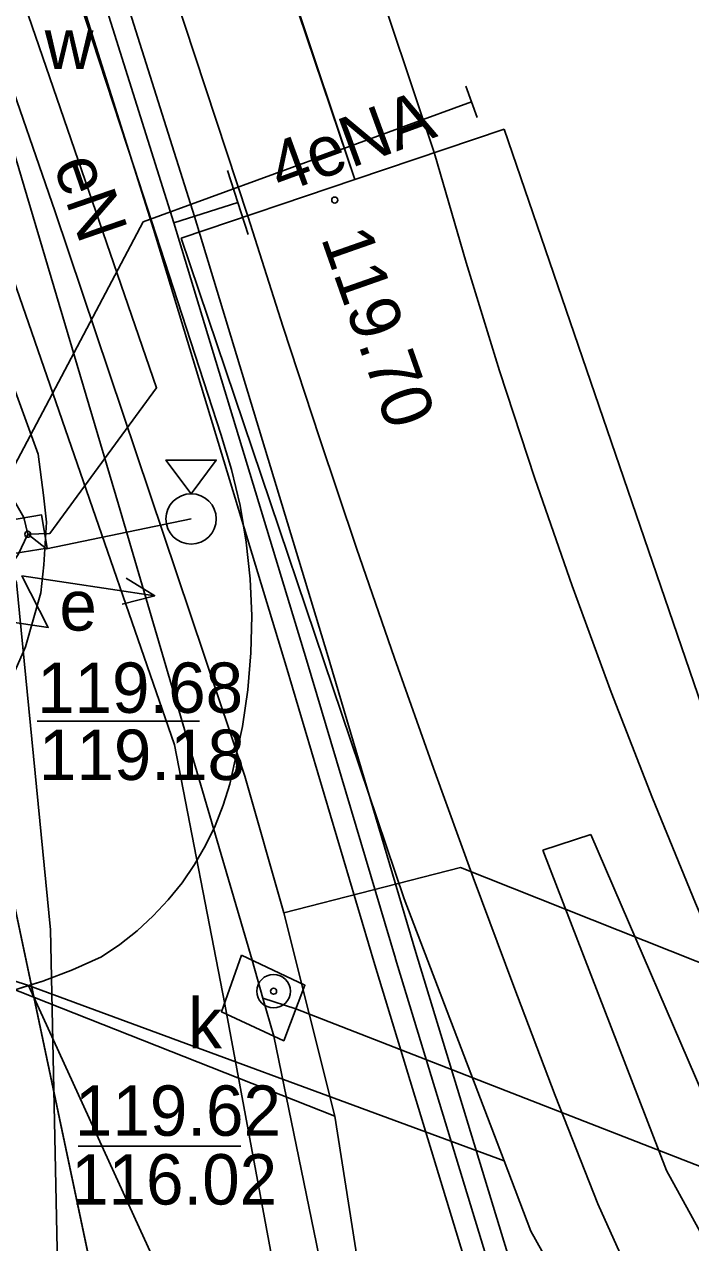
# Model space of a CAD drawing. Extents: x 6432121 to 6432331, y 5662538 to 5662686.
# Drawn here: x 6432264.87 to 6432274.79, y 5662575.8 to 5662593.95 of the extents above; entities that cross this region are included whole.
import ezdxf

# ---------------------------------------------------------------- set-up
doc = ezdxf.new("R2010")
doc.units = 0
for name, color, linetype in [('Warstwa 1', 7, 'Continuous'), ('Warstwa 12', 7, 'Continuous'), ('Warstwa 13', 7, 'Continuous'), ('Warstwa 14', 7, 'Continuous'), ('Warstwa 15', 7, 'Continuous'), ('Warstwa 16', 7, 'Continuous'), ('Warstwa 19', 7, 'Continuous'), ('Warstwa 20', 7, 'Continuous'), ('Warstwa 25', 7, 'Continuous'), ('Warstwa 37', 7, 'Continuous'), ('Warstwa 4', 7, 'Continuous'), ('Warstwa 40', 7, 'Continuous'), ('Warstwa 5', 7, 'Continuous'), ('Warstwa 6', 7, 'Continuous'), ('Warstwa 61', 7, 'Continuous'), ('Warstwa 8', 7, 'Continuous'), ('Warstwa 9', 7, 'Continuous')]:
    doc.layers.add(name, color=color, linetype=linetype)

msp = doc.modelspace()

# ---------------------------------------------------------------- linework, layer by layer
at = {"layer": 'Warstwa 1'}
msp.add_line((6432263.163, 5662588.197), (6432269.007, 5662560.534), dxfattribs=at)
msp.add_line((6432263.163, 5662588.197), (6432269.007, 5662560.534), dxfattribs=at)
at = {"layer": 'Warstwa 12'}
for points in [[(6432244.451, 5662661.055), (6432244.51, 5662660.562), (6432244.747, 5662659.597), (6432247.148, 5662651.498), (6432250.159, 5662641.297), (6432254.564, 5662626.481), (6432257.548, 5662616.394), (6432260.807, 5662605.248), (6432262.453, 5662599.664), (6432266.272, 5662586.802), (6432268.265, 5662580.011), (6432268.423, 5662579.446)], [(6432243.958, 5662654.289), (6432246.621, 5662646.365), (6432250.032, 5662636.381), (6432251.998, 5662630.56), (6432253.864, 5662624.956), (6432256.122, 5662618.174), (6432258.071, 5662612.417), (6432261.076, 5662603.597), (6432261.907, 5662601.278), (6432263.382, 5662596.576), (6432264.52, 5662593.503), (6432265.328, 5662591.162), (6432268.156, 5662582.752), (6432268.733, 5662580.715)], [(6432243.16, 5662653.357), (6432252.465, 5662626.114), (6432254.893, 5662619.007), (6432257.883, 5662610.233), (6432261.03, 5662600.869), (6432263.754, 5662592.896), (6432267.107, 5662583.22), (6432267.857, 5662579.356), (6432269.061, 5662572.854)], [(6432156.818, 5662630.202), (6432158.039, 5662625.384), (6432159.105, 5662620.911), (6432168.554, 5662616.714), (6432182.01, 5662611.519), (6432201.034, 5662604.23), (6432217.284, 5662598.028), (6432236.124, 5662590.737), (6432242.639, 5662588.267), (6432252.12, 5662584.559), (6432258.988, 5662581.806), (6432263.17, 5662580.184), (6432269.496, 5662577.686)], [(6432264.921, 5662586.356), (6432264.864, 5662586.606), (6432260.124, 5662594.894), (6432256.835, 5662605.655), (6432256.691, 5662608.587), (6432255.365, 5662611.413), (6432254.697, 5662614.101), (6432250.901, 5662625.148), (6432249.199, 5662629.099), (6432249.05, 5662629.25)], [(6432262.524, 5662606.965), (6432264.736, 5662599.765), (6432265.711, 5662596.619), (6432266.353, 5662594.428), (6432267.404, 5662591.09), (6432269.38, 5662584.578), (6432270.703, 5662580.126), (6432272.6, 5662573.902), (6432271.988, 5662573.716), (6432270.091, 5662579.942), (6432268.768, 5662584.394), (6432266.792, 5662590.9), (6432265.741, 5662594.242), (6432265.099, 5662596.435), (6432264.124, 5662599.577), (6432261.914, 5662606.769)], [(6432264.68, 5662595.96), (6432264.34, 5662595.79), (6432266.84, 5662588.54), (6432265.25, 5662586.37), (6432264.921, 5662586.356)], [(6432271.286, 5662556.053), (6432270.085, 5662562.791), (6432268.957, 5662564.575), (6432265.556, 5662566.187), (6432265.259, 5662580.461), (6432264.752, 5662585.638), (6432260.149, 5662593.584)], [(6432261.14, 5662584.03), (6432263.32, 5662584.73), (6432266.64, 5662591.01), (6432271.53, 5662592.8)], [(6432264.921, 5662586.356), (6432265.198, 5662586.142), (6432267.354, 5662586.586)], [(6432256.793, 5662568.811), (6432256.973, 5662569.251), (6432261.624, 5662580.855), (6432261.7, 5662581.364), (6432261.906, 5662581.802), (6432264.777, 5662586.057), (6432264.921, 5662586.356)], [(6432288.268, 5662574.665), (6432287.596, 5662574.929), (6432279.572, 5662578.128), (6432271.367, 5662581.39), (6432268.733, 5662580.715)], [(6432268.733, 5662580.715), (6432269.496, 5662577.686)], [(6432268.423, 5662579.446), (6432268.584, 5662578.879), (6432270.527, 5662569.427), (6432271.399, 5662565.796), (6432272.457, 5662560.429), (6432273.245, 5662557.108), (6432273.455, 5662556.053)], [(6432268.423, 5662579.446), (6432268.914, 5662579.286), (6432283.177, 5662573.724), (6432291.711, 5662570.445), (6432298.653, 5662567.696), (6432305.047, 5662565.259), (6432317.636, 5662560.353), (6432325.976, 5662557.133)], [(6432269.496, 5662577.686), (6432270.733, 5662569.814), (6432272.063, 5662561.483), (6432272.925, 5662556.053)]]:
    msp.add_lwpolyline(points, dxfattribs=at)
at = {"layer": 'Warstwa 14'}
for p, q in [((6432265.062, 5662583.571), (6432267.48, 5662583.571)), ((6432265.673, 5662577.242), (6432268.096, 5662577.242))]:
    msp.add_line(p, q, dxfattribs=at)
for centre in [(6432264.921, 5662586.356), (6432264.921, 5662586.356), (6432268.582, 5662579.549), (6432268.582, 5662579.549)]:
    msp.add_circle(centre, 0.045, dxfattribs=at)
at = {"layer": 'Warstwa 16'}
msp.add_lwpolyline([(6432268.106, 5662580.087), (6432269.049, 5662579.637), (6432268.733, 5662578.81), (6432267.805, 5662579.244)], close=True, dxfattribs=at)
at = {"layer": 'Warstwa 19'}
for p, q in [((6432267.898, 5662591.776), (6432268.203, 5662590.823)), ((6432267.098, 5662590.995), (6432268.051, 5662591.299))]:
    msp.add_line(p, q, dxfattribs=at)
at = {"layer": 'Warstwa 20'}
msp.add_line((6432271.444, 5662593.035), (6432271.616, 5662592.565), dxfattribs=at)
at = {"layer": 'Warstwa 25'}
msp.add_circle((6432269.493, 5662591.336), 0.045, dxfattribs=at)
at = {"layer": 'Warstwa 37'}
for points in [[(6432270.98, 5662592.032), (6432263.223, 5662615.178), (6432259.09, 5662627.49)], [(6432268.199, 5662591.096), (6432259.533, 5662617.358), (6432256.37, 5662626.58)], [(6432270.98, 5662592.032), (6432271.449, 5662590.408), (6432271.947, 5662588.793), (6432272.474, 5662587.187), (6432273.03, 5662585.59), (6432273.613, 5662584.003), (6432274.225, 5662582.427), (6432274.865, 5662580.863), (6432275.532, 5662579.309), (6432276.227, 5662577.768)], [(6432268.199, 5662591.096), (6432268.725, 5662589.442), (6432269.264, 5662587.794), (6432269.817, 5662586.149), (6432270.383, 5662584.51), (6432270.962, 5662582.874), (6432271.554, 5662581.244), (6432272.16, 5662579.618), (6432272.778, 5662577.997), (6432273.41, 5662576.382)], [(6432273.41, 5662576.382), (6432273.789, 5662575.542), (6432274.199, 5662574.716), (6432274.639, 5662573.907), (6432275.109, 5662573.114), (6432275.607, 5662572.339), (6432276.134, 5662571.582), (6432276.688, 5662570.846), (6432277.269, 5662570.13), (6432277.876, 5662569.437)]]:
    msp.add_lwpolyline(points, dxfattribs=at)
at = {"layer": 'Warstwa 4'}
msp.add_lwpolyline([(6432264.633, 5662586.562), (6432264.715, 5662586.068), (6432265.209, 5662586.15), (6432265.127, 5662586.644)], close=True, dxfattribs=at)
msp.add_circle((6432268.582, 5662579.549), 0.25, dxfattribs=at)
at = {"layer": 'Warstwa 40'}
msp.add_lwpolyline([(6432267.354, 5662586.961), (6432266.979, 5662587.461), (6432267.729, 5662587.461)], close=True, dxfattribs=at)
for points in [[(6432263.247, 5662585.263), (6432265.226, 5662584.969), (6432264.834, 5662585.735), (6432266.812, 5662585.441)], [(6432266.386, 5662585.702), (6432266.812, 5662585.441), (6432266.328, 5662585.315)]]:
    msp.add_lwpolyline(points, dxfattribs=at)
msp.add_circle((6432267.354, 5662586.586), 0.375, dxfattribs=at)
at = {"layer": 'Warstwa 6'}
for points in [[(6432295.199, 5662556.053), (6432289.811, 5662577.223), (6432287.64, 5662583.69), (6432267.75, 5662642.76), (6432246.69, 5662636.13), (6432263.163, 5662588.197), (6432269.007, 5662560.534), (6432269.756, 5662556.053)], [(6432253.68, 5662630.32), (6432261.638, 5662606.697), (6432266.51, 5662591.804), (6432267.797, 5662587.848)], [(6432257.996, 5662627.099), (6432261.912, 5662615.276), (6432267.276, 5662599.098), (6432269.793, 5662591.641)], [(6432267.797, 5662587.848), (6432267.957, 5662587.32), (6432268.083, 5662586.783), (6432268.175, 5662586.239), (6432268.233, 5662585.691), (6432268.256, 5662585.139), (6432268.244, 5662584.588), (6432268.198, 5662584.038), (6432268.117, 5662583.493), (6432268.002, 5662582.953)], [(6432268.002, 5662582.953), (6432267.929, 5662582.633), (6432267.832, 5662582.32), (6432267.712, 5662582.015), (6432267.569, 5662581.719), (6432267.404, 5662581.436), (6432267.219, 5662581.165), (6432267.013, 5662580.909), (6432266.789, 5662580.67), (6432266.548, 5662580.448), (6432266.291, 5662580.244), (6432266.019, 5662580.061)], [(6432266.019, 5662580.061), (6432265.588, 5662579.868), (6432265.146, 5662579.7), (6432264.696, 5662579.557), (6432264.239, 5662579.441), (6432263.775, 5662579.35), (6432263.307, 5662579.286), (6432262.836, 5662579.248), (6432262.364, 5662579.238), (6432261.892, 5662579.254)]]:
    msp.add_lwpolyline(points, dxfattribs=at)
msp.add_lwpolyline([(6432180.9, 5662615.82), (6432147.05, 5662605.45), (6432141.907, 5662600.47), (6432155.186, 5662604.45), (6432246.621, 5662569.177), (6432269.007, 5662560.534), (6432263.163, 5662588.197), (6432259.074, 5662585.787)], close=True, dxfattribs=at)
at = {"layer": 'Warstwa 61'}
msp.add_lwpolyline([(6432262.219, 5662606.867), (6432264.43, 5662599.671), (6432265.405, 5662596.527), (6432266.047, 5662594.335), (6432267.098, 5662590.995), (6432269.074, 5662584.486), (6432270.397, 5662580.035), (6432270.397, 5662580.033), (6432272.294, 5662573.809)], dxfattribs=at)
at = {"layer": 'Warstwa 8'}
for p, q in [((6432258.72, 5662624.914), (6432269.793, 5662591.641)), ((6432261.638, 5662606.697), (6432266.51, 5662591.804)), ((6432267.276, 5662599.098), (6432269.793, 5662591.641)), ((6432269.793, 5662591.641), (6432272.015, 5662592.39)), ((6432269.793, 5662591.641), (6432272.015, 5662592.39)), ((6432272.015, 5662592.39), (6432275.347, 5662582.659)), ((6432272.015, 5662592.39), (6432275.347, 5662582.659)), ((6432266.51, 5662591.804), (6432267.797, 5662587.848)), ((6432267.205, 5662590.768), (6432269.793, 5662591.641)), ((6432267.205, 5662590.768), (6432269.793, 5662591.641)), ((6432267.205, 5662590.768), (6432270.525, 5662580.927)), ((6432267.205, 5662590.768), (6432270.525, 5662580.927)), ((6432267.797, 5662587.848), (6432267.957, 5662587.32)), ((6432267.957, 5662587.32), (6432268.083, 5662586.783)), ((6432268.083, 5662586.783), (6432268.175, 5662586.239)), ((6432268.175, 5662586.239), (6432268.233, 5662585.691)), ((6432268.233, 5662585.691), (6432268.256, 5662585.139)), ((6432268.244, 5662584.588), (6432268.256, 5662585.139)), ((6432268.198, 5662584.038), (6432268.244, 5662584.588)), ((6432268.117, 5662583.493), (6432268.198, 5662584.038)), ((6432268.002, 5662582.953), (6432268.117, 5662583.493)), ((6432267.929, 5662582.633), (6432268.002, 5662582.953)), ((6432267.832, 5662582.32), (6432267.929, 5662582.633)), ((6432267.712, 5662582.015), (6432267.832, 5662582.32)), ((6432267.569, 5662581.719), (6432267.712, 5662582.015)), ((6432272.594, 5662581.652), (6432273.307, 5662581.884)), ((6432272.594, 5662581.652), (6432273.307, 5662581.884)), ((6432273.307, 5662581.884), (6432275.282, 5662577.299)), ((6432273.307, 5662581.884), (6432275.282, 5662577.299)), ((6432267.404, 5662581.436), (6432267.569, 5662581.719)), ((6432272.594, 5662581.652), (6432274.436, 5662576.88)), ((6432272.594, 5662581.652), (6432274.436, 5662576.88)), ((6432267.219, 5662581.165), (6432267.404, 5662581.436)), ((6432267.013, 5662580.909), (6432267.219, 5662581.165)), ((6432266.789, 5662580.67), (6432267.013, 5662580.909)), ((6432270.525, 5662580.927), (6432272.015, 5662577.021)), ((6432270.525, 5662580.927), (6432272.015, 5662577.021)), ((6432266.548, 5662580.448), (6432266.789, 5662580.67)), ((6432266.291, 5662580.244), (6432266.548, 5662580.448)), ((6432266.019, 5662580.061), (6432266.291, 5662580.244)), ((6432265.588, 5662579.868), (6432266.019, 5662580.061)), ((6432264.933, 5662579.632), (6432265.146, 5662579.7)), ((6432265.146, 5662579.7), (6432265.588, 5662579.868)), ((6432264.696, 5662579.557), (6432264.933, 5662579.632)), ((6432264.933, 5662579.632), (6432269.167, 5662570.383)), ((6432264.933, 5662579.632), (6432272.015, 5662577.021)), ((6432264.933, 5662579.632), (6432272.015, 5662577.021)), ((6432264.933, 5662579.632), (6432269.167, 5662570.383)), ((6432272.015, 5662577.021), (6432272.415, 5662575.974)), ((6432272.015, 5662577.021), (6432272.415, 5662575.974)), ((6432274.436, 5662576.88), (6432276.882, 5662572.4)), ((6432274.436, 5662576.88), (6432276.882, 5662572.4)), ((6432272.415, 5662575.974), (6432275.126, 5662571.121)), ((6432272.415, 5662575.974), (6432275.126, 5662571.121))]:
    msp.add_line(p, q, dxfattribs=at)
at = {"layer": 'Warstwa 9'}
for p, q in [((6432261.638, 5662606.697), (6432266.51, 5662591.804)), ((6432266.51, 5662591.804), (6432267.797, 5662587.848)), ((6432264.041, 5662590.381), (6432265.076, 5662587.55)), ((6432264.041, 5662590.381), (6432265.076, 5662587.55)), ((6432267.797, 5662587.848), (6432267.957, 5662587.32)), ((6432265.076, 5662587.55), (6432265.156, 5662586.941)), ((6432265.076, 5662587.55), (6432265.156, 5662586.941)), ((6432267.957, 5662587.32), (6432268.083, 5662586.783)), ((6432265.156, 5662586.941), (6432265.201, 5662586.538)), ((6432265.156, 5662586.941), (6432265.201, 5662586.538)), ((6432268.083, 5662586.783), (6432268.175, 5662586.239)), ((6432265.16, 5662585.899), (6432265.201, 5662586.538)), ((6432265.16, 5662585.899), (6432265.201, 5662586.538)), ((6432268.175, 5662586.239), (6432268.233, 5662585.691)), ((6432265.116, 5662585.482), (6432265.16, 5662585.899)), ((6432265.116, 5662585.482), (6432265.16, 5662585.899)), ((6432268.233, 5662585.691), (6432268.256, 5662585.139)), ((6432264.889, 5662584.681), (6432265.116, 5662585.482)), ((6432264.889, 5662584.681), (6432265.116, 5662585.482)), ((6432268.244, 5662584.588), (6432268.256, 5662585.139)), ((6432264.662, 5662584.168), (6432264.889, 5662584.681)), ((6432264.662, 5662584.168), (6432264.889, 5662584.681)), ((6432268.198, 5662584.038), (6432268.244, 5662584.588)), ((6432268.117, 5662583.493), (6432268.198, 5662584.038)), ((6432268.002, 5662582.953), (6432268.117, 5662583.493)), ((6432267.929, 5662582.633), (6432268.002, 5662582.953)), ((6432267.832, 5662582.32), (6432267.929, 5662582.633)), ((6432267.712, 5662582.015), (6432267.832, 5662582.32)), ((6432267.569, 5662581.719), (6432267.712, 5662582.015)), ((6432267.404, 5662581.436), (6432267.569, 5662581.719)), ((6432267.219, 5662581.165), (6432267.404, 5662581.436)), ((6432267.013, 5662580.909), (6432267.219, 5662581.165)), ((6432266.789, 5662580.67), (6432267.013, 5662580.909)), ((6432266.548, 5662580.448), (6432266.789, 5662580.67)), ((6432262.133, 5662580.563), (6432264.933, 5662579.632)), ((6432262.133, 5662580.563), (6432264.933, 5662579.632)), ((6432266.291, 5662580.244), (6432266.548, 5662580.448)), ((6432266.019, 5662580.061), (6432266.291, 5662580.244)), ((6432265.588, 5662579.868), (6432266.019, 5662580.061)), ((6432264.933, 5662579.632), (6432265.146, 5662579.7)), ((6432265.146, 5662579.7), (6432265.588, 5662579.868)), ((6432264.696, 5662579.557), (6432264.933, 5662579.632)), ((6432264.933, 5662579.632), (6432264.933, 5662579.632))]:
    msp.add_line(p, q, dxfattribs=at)

# ---------------------------------------------------------------- texts
at = {"layer": 'Warstwa 13'}
for s, rotation, p in [('4eNA', 20.1051, (6432268.687, 5662591.427)), ('eN', 289.0228, (6432265.296, 5662591.866))]:
    msp.add_text(s, height=0.75, rotation=rotation, dxfattribs=at).set_placement(p)
at = {"layer": 'Warstwa 14'}
for s, p in [('119.18', (6432265.088, 5662582.696)), ('116.02', (6432265.567, 5662576.371))]:
    msp.add_text(s, height=0.75, dxfattribs=at).set_placement(p)
at = {"layer": 'Warstwa 15'}
for s, p in [('119.68', (6432265.06, 5662583.696)), ('119.62', (6432265.624, 5662577.395))]:
    msp.add_text(s, height=0.75, dxfattribs=at).set_placement(p)
at = {"layer": 'Warstwa 25'}
msp.add_text('119.70', height=0.75, rotation=289.3494, dxfattribs=at).set_placement((6432269.283, 5662590.772))
at = {"layer": 'Warstwa 5'}
for s, p in [('w', (6432265.174, 5662593.287)), ('e', (6432265.392, 5662584.922)), ('k', (6432267.311, 5662578.697))]:
    msp.add_text(s, height=0.75, dxfattribs=at).set_placement(p)

doc.saveas('drawing.dxf')
